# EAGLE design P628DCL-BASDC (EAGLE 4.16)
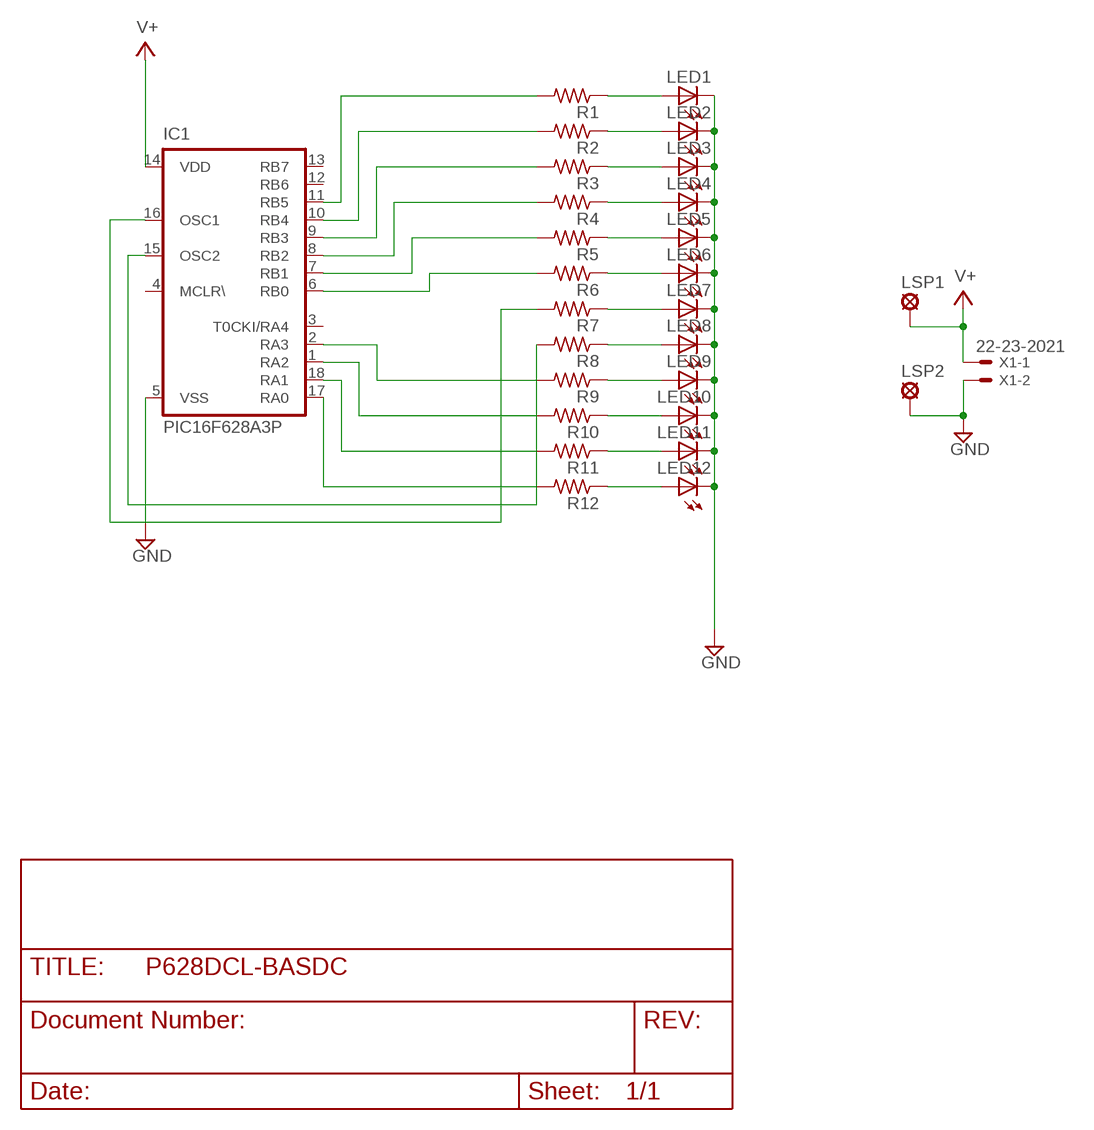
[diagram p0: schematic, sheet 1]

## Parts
IC1  PIC16F628A3P  [DIL18]
LED1  LEDLZR181  [LZR181]
LED2  LEDLZR181  [LZR181]
LED3  LEDLZR181  [LZR181]
LED4  LEDLZR181  [LZR181]
LED5  LEDLZR181  [LZR181]
LED6  LEDLZR181  [LZR181]
LED7  LEDLZR181  [LZR181]
LED8  LEDLZR181  [LZR181]
LED9  LEDLZR181  [LZR181]
LED10  LEDLZR181  [LZR181]
LED11  LEDLZR181  [LZR181]
LED12  LEDLZR181  [LZR181]
LSP1  LSP10  [LSP10]
LSP2  LSP10  [LSP10]
R1  R-US_0204/7  [0204/7]
R2  R-US_0204/7  [0204/7]
R3  R-US_0204/7  [0204/7]
R4  R-US_0204/7  [0204/7]
R5  R-US_0204/7  [0204/7]
R6  R-US_0204/7  [0204/7]
R7  R-US_0204/7  [0204/7]
R8  R-US_0204/7  [0204/7]
R9  R-US_0204/7  [0204/7]
R10  R-US_0204/7  [0204/7]
R11  R-US_0204/7  [0204/7]
R12  R-US_0204/7  [0204/7]
X1  22-23-2021  [22-23-2021]

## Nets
GND: IC1.5(VSS) LED1.K(C) LED2.K(C) LED3.K(C) LED4.K(C) LED5.K(C) LED6.K(C) LED7.K(C) LED8.K(C) LED9.K(C) LED10.K(C) LED11.K(C) LED12.K(C) LSP2.MP X1.2
N$1: IC1.15(OSC2) R8.2
N$2: LED1.A R1.1
N$3: LED2.A R2.1
N$4: LED3.A R3.1
N$5: LED4.A R4.1
N$6: LED5.A R5.1
N$7: LED6.A R6.1
N$8: LED7.A R7.1
N$9: LED8.A R8.1
N$10: LED9.A R9.1
N$11: LED10.A R10.1
N$12: LED11.A R11.1
N$13: LED12.A R12.1
N$14: IC1.16(OSC1) R7.2
N$17: IC1.17(RA0) R12.2
N$18: IC1.18(RA1) R11.2
N$19: IC1.1(RA2) R10.2
N$20: IC1.2(RA3) R9.2
N$22: IC1.10(RB4) R2.2
N$23: IC1.9(RB3) R3.2
N$24: IC1.8(RB2) R4.2
N$25: IC1.7(RB1) R5.2
N$26: IC1.6(RB0) R6.2
N$29: IC1.11(RB5) R1.2
V+: IC1.14(VDD) LSP1.MP X1.1
Unconnected: IC1.3(T0CKI/RA4) IC1.4(MCLR\) IC1.12(RB6) IC1.13(RB7)

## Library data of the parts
IC1 = microchip:PIC16F628A: MICROCONTROLLER 8-Bit PIC16F8X Family - CMOS Flash/EEPROM Pin Compatible : PIC16F83, PIC16CR83, PIC16F84A, PIC16CR84 see also PIC16C*
LED1-LED12 = led:LED: LED
LSP1 LSP2 = solpad:LSP10: SOLDER PAD
R1-R12 = rcl:R-US_: RESISTOR, American symbol
X1 = con-molex:22-23-2021: .100" (2.54mm) Center Header - 2 Pin

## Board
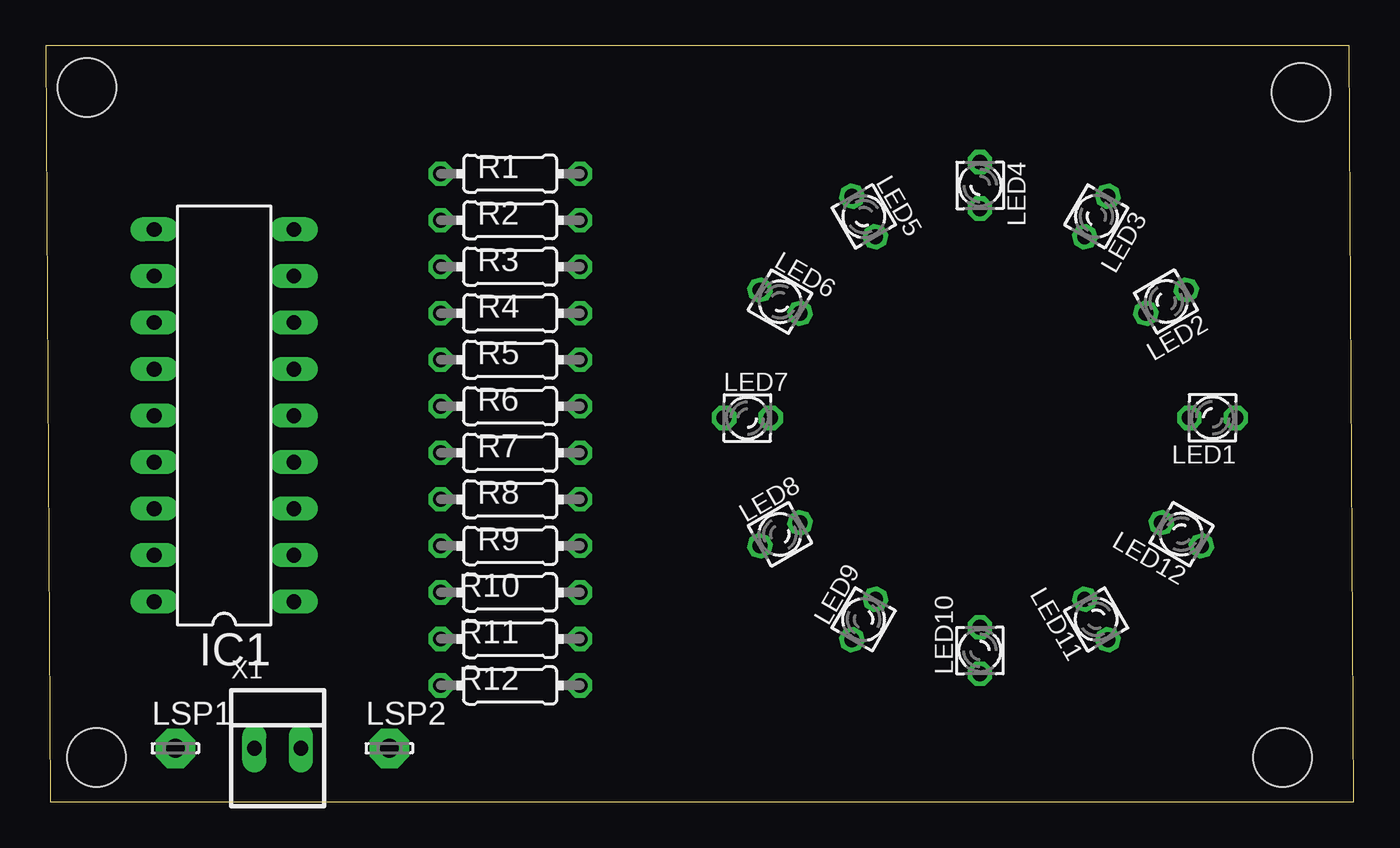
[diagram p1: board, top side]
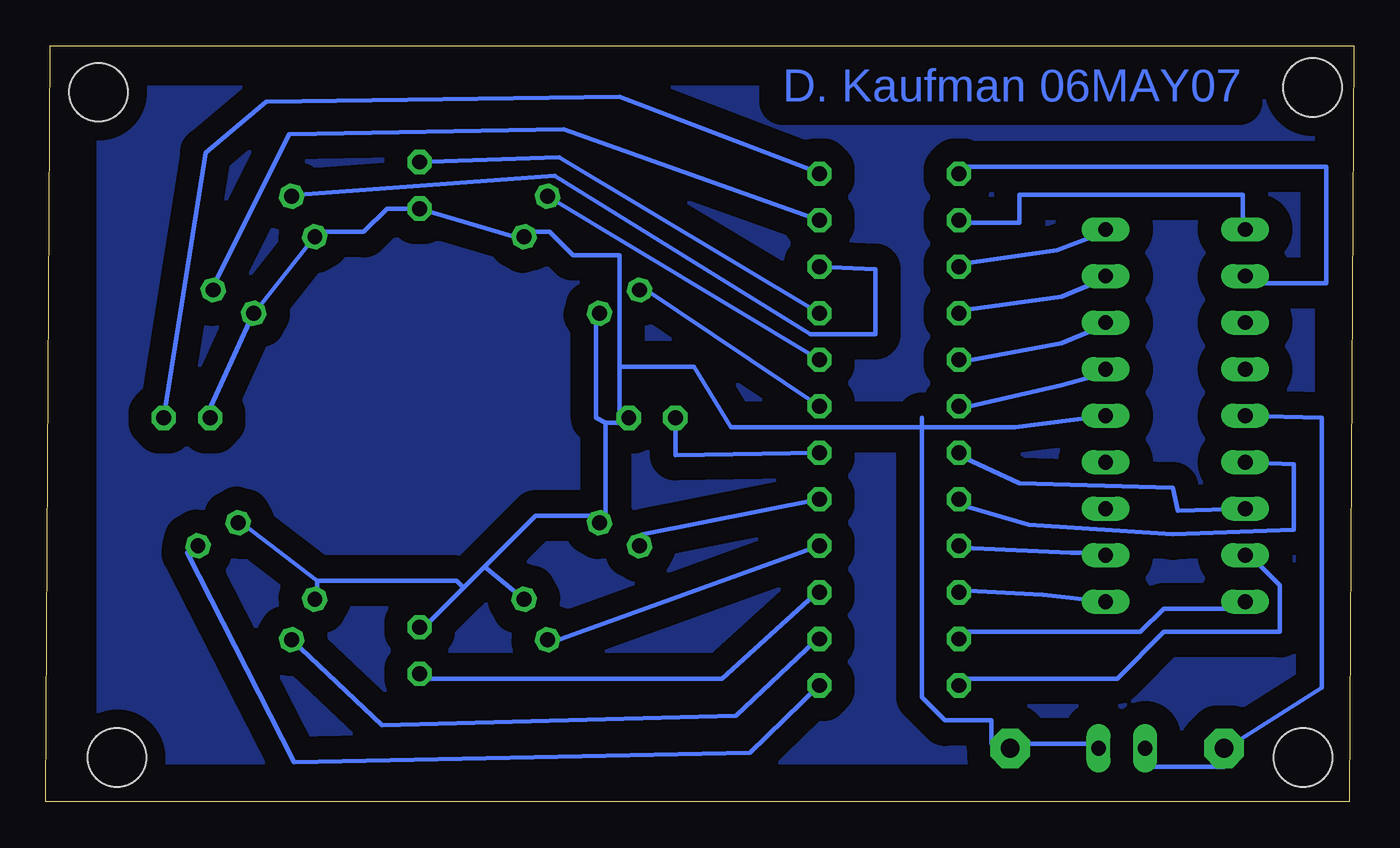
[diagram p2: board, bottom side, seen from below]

Size 71.42 x 41.27 mm. Coordinates in mm from the lower left corner, seen from the top.
Outline: 0.25,0 71.42,0 71.17,41.27 0,41.27 0.25,0
Copper layers (1*16): Top 0.035mm / dielectric 1.5mm / Bottom 0.035mm
Design rules "polywide": minimum track width 10mil, minimum drill 24mil, track to track 50mil, track to pad 50mil, pad to pad 50mil, via to via 50mil, smd to smd 8mil, copper to edge 40mil, drill to drill 50mil, minimum pad ring 10mil, minimum via ring 8mil, stop-mask expansion 4mil, vias tented up to drill 0mil, thermal gap 10mil
Holes 3.2 mm at 2.25,38.98 2.76,2.41 67.53,2.41 68.54,38.73

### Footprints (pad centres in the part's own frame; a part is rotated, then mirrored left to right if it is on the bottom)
DIL18 = drill 0.813 long: 1 -10.16,-3.81; 2 -7.62,-3.81; 3 -5.08,-3.81; 4 -2.54,-3.81; 5 0,-3.81; 6 2.54,-3.81; 7 5.08,-3.81; 8 7.62,-3.81; 9 10.16,-3.81; 10 10.16,3.81; 11 7.62,3.81; 12 5.08,3.81; 13 2.54,3.81; 14 0,3.81; 15 -2.54,3.81; 16 -5.08,3.81; 17 -7.62,3.81; 18 -10.16,3.81
LZR181 = drill 0.813 octagon: A -1.27,0; K 1.27,0
LSP10 = drill 1.016 pad 2.159 octagon: MP 0,0
0204/7 = drill 0.813 octagon: 1 -3.81,0; 2 3.81,0
22-23-2021 = drill 0.813 long: 1 -1.27,0; 2 1.27,0

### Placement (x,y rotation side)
IC1  9.74,21.08 90 top
LED1  63.72,20.95 180 top
LED2  61.18,27.3 210 top
LED3  57.37,31.95 240 top
LED4  51.02,33.65 270 top
LED5  44.67,31.95 300 top
LED6  40.09,27.3 330 top
LED7  38.32,20.95 0 top
LED8  40.09,14.6 30 top
LED9  44.67,9.95 60 top
LED10  51.02,8.25 90 top
LED11  57.37,9.95 120 top
LED12  62.01,14.6 150 top
LSP1  7.07,2.92 0 top
LSP2  18.76,2.92 0 top
R1  25.36,34.29 180 top
R2  25.36,31.74 180 top
R3  25.36,29.2 180 top
R4  25.36,26.66 180 top
R5  25.36,24.12 180 top
R6  25.36,21.58 180 top
R7  25.36,19.04 180 top
R8  25.36,16.5 180 top
R9  25.36,13.97 180 top
R10  25.36,11.43 180 top
R11  25.36,8.89 180 top
R12  25.36,6.34 180 top
X1  12.66,2.92 0 top

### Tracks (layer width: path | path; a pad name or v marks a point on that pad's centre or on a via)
GND
  Bottom 0.254: 40.86,20.7 40.86,15.62 | 40.86,20.7 39.59,20.7 LED7.K 40.09,20.95 40.09,23.74 | 47.46,12.82 44.67,15.62 40.86,15.62 | 47.46,12.82 48.6,11.68 | 48.6,11.68 51.02,9.27 LED10.K | 40.86,15.62 LED8.K | 47.46,12.82 LED9.K | 60.16,26.54 LED3.K 56.6,31.11 54.06,31.11 52.79,32.38 LED4.K 45.94,30.86 LED5.K 45.17,31.11 43.9,31.11 42.63,29.84 40.09,29.84 40.09,23.74 | LED1.K 62.7,20.95 60.16,26.54 | 60.16,26.54 LED2.K | LED6.K 41.36,26.03 41.36,20.95 40.86,20.7 | IC1.5 18.5,20.44 23.58,20.44 | 23.58,20.44 34,20.44 36.03,23.74 40.09,23.74 | 56.6,12.06 56.6,10.79 LED11.K | 56.6,12.06 48.98,12.06 48.6,11.68 | LED12.K 60.92,15.36 56.6,12.06 | X1.2 13.42,3.17 18.5,3.17 LSP2.MP 19.77,3.17 19.77,4.44 22.31,4.44 23.58,5.71 23.58,20.44 | 23.58,20.44 23.58,20.95
N$1
  Bottom 0.254: IC1.15 3.26,18.41 3.26,14.85 9.87,14.6 17.74,15.11 22.06,16.38 21.55,16.38 R8.2
N$2
  Bottom 0.254: LED1.A 62.7,35.43 59.4,38.22 40.09,38.48 29.43,34.41 R1.1
N$3
  Bottom 0.254: R2.1 43.14,36.7 58.13,36.44 62.45,27.81 LED2.A
N$4
  Bottom 0.254: R3.1 26.12,29.08 26.12,25.52 29.68,25.52 43.65,34.16 57.62,33.14 LED3.A
N$5
  Bottom 0.254: R4.1 43.4,35.17 51.27,34.92 LED4.A
N$6
  Bottom 0.254: LED5.A 44.16,33.14 R5.1
N$7
  Bottom 0.254: LED6.A 38.82,28.06 R6.1
N$8
  Bottom 0.254: R7.1 37.05,18.92 LED7.A
N$9
  Bottom 0.254: R8.1 38.82,14.6 38.57,13.58 39.08,14.09 LED8.A
N$10
  Bottom 0.254: LED9.A 43.65,8.76 R9.1
N$11
  Bottom 0.254: R10.1 29.17,11.55 34.51,6.73 51.02,6.73 LED10.A
N$12
  Bottom 0.254: LED11.A 53.05,4.19 33.74,4.69 29.43,8.76 R11.1
N$13
  Bottom 0.254: R12.1 32.98,2.66 57.87,2.15 63.72,13.58 63.21,13.84 LED12.A
N$14
  Bottom 0.254: IC1.16 9.61,15.87 9.87,17.14 18.25,17.39 21.55,18.92 R7.2
N$16
  pour Bottom: 2.25,38.98 68.54,38.98 68.54,2.15 2.25,2.15
N$17
  Bottom 0.254: IC1.17 5.3,13.08 4.03,11.81 4.03,9.27 10.38,9.27 12.92,6.73 21.81,6.73 R12.2
N$18
  Bottom 0.254: IC1.18 6.57,10.54 10.38,10.54 11.65,9.27 21.81,9.27 R11.2
N$19
  Bottom 0.254: IC1.1 16.98,11.3 21.55,11.55 R10.2
N$20
  Bottom 0.254: IC1.2 14.69,13.58 15.46,13.58 20.79,13.84 R9.2
N$22
  Bottom 0.254: IC1.10 6.06,31.24 6.06,33.14 18.25,33.14 18.25,31.62 21.3,31.62 21.3,31.74 | 21.3,31.74 21.3,31.87 | 21.3,31.74 R2.2
N$23
  Bottom 0.254: IC1.9 14.19,30.86 16.22,30.09 21.55,29.33 R3.2
N$24
  Bottom 0.254: IC1.8 14.19,28.32 15.96,27.55 21.55,26.79 R4.2
N$25
  Bottom 0.254: IC1.7 14.19,25.78 15.96,25.01 21.55,24 R5.2
N$26
  Bottom 0.254: IC1.6 14.19,23.24 15.96,22.73 21.55,21.46 R6.2
N$29
  Bottom 0.254: IC1.11 5.3,28.32 1.49,28.32 1.49,34.67 21.81,34.67 R1.2
V+
  Bottom 0.254: X1.1 10.88,1.9 7.07,1.9 LSP1.MP 7.33,2.66 1.74,6.22 1.74,20.95 IC1.14

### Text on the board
Bottom: D. Kaufman 06MAY07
